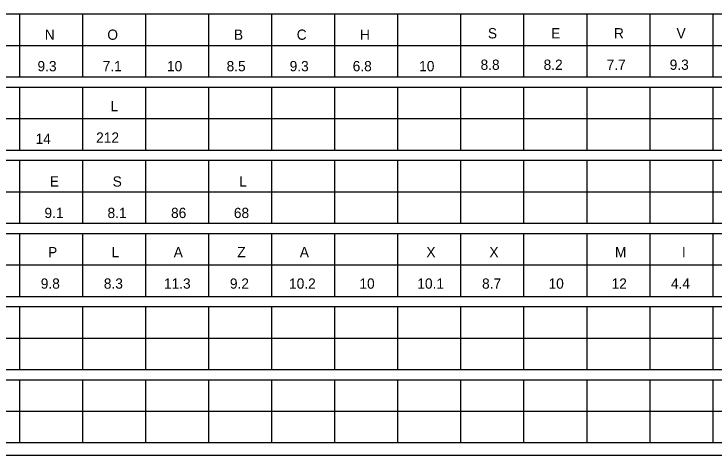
# Model space of a CAD drawing. Extents: x 17890628 to 17890817, y 17897493 to 17897992.
# Drawn here: x 17890684.37 to 17890717.8, y 17897548.86 to 17897569.94 of the extents above; entities that cross this region are included whole.
import ezdxf

# ---------------------------------------------------------------- set-up
doc = ezdxf.new("R2010")
doc.units = 0
doc.layers.add('GSSign', color=7, linetype='Continuous')
doc.layers.add('SheetLinesMisc2_dp', color=7, linetype='Continuous')

msp = doc.modelspace()

# ---------------------------------------------------------------- linework, layer by layer
at = {"layer": 'SheetLinesMisc2_dp'}
for p, q in [((17890661.804, 17897569.94), (17890735.8, 17897569.94)), ((17890684.628, 17897569.94), (17890684.628, 17897566.933)), ((17890687.638, 17897569.94), (17890687.638, 17897566.933)), ((17890690.648, 17897569.94), (17890690.648, 17897566.933)), ((17890693.658, 17897569.94), (17890693.658, 17897566.933)), ((17890696.669, 17897569.94), (17890696.669, 17897566.933)), ((17890699.679, 17897569.94), (17890699.679, 17897566.933)), ((17890702.689, 17897569.94), (17890702.689, 17897566.933)), ((17890705.699, 17897569.94), (17890705.699, 17897566.933)), ((17890708.709, 17897569.94), (17890708.709, 17897566.933)), ((17890711.719, 17897569.94), (17890711.719, 17897566.933)), ((17890714.729, 17897569.94), (17890714.729, 17897566.933)), ((17890717.739, 17897569.94), (17890717.739, 17897566.933)), ((17890661.804, 17897568.437), (17890735.8, 17897568.437)), ((17890661.804, 17897566.933), (17890735.8, 17897566.933)), ((17890661.804, 17897566.443), (17890735.8, 17897566.443)), ((17890684.628, 17897566.443), (17890684.628, 17897563.437)), ((17890687.638, 17897566.443), (17890687.638, 17897563.437)), ((17890690.648, 17897566.443), (17890690.648, 17897563.437)), ((17890693.658, 17897566.443), (17890693.658, 17897563.437)), ((17890696.669, 17897566.443), (17890696.669, 17897563.437)), ((17890699.679, 17897566.443), (17890699.679, 17897563.437)), ((17890702.689, 17897566.443), (17890702.689, 17897563.437)), ((17890705.699, 17897566.443), (17890705.699, 17897563.437)), ((17890708.709, 17897566.443), (17890708.709, 17897563.437)), ((17890711.719, 17897566.443), (17890711.719, 17897563.437)), ((17890714.729, 17897566.443), (17890714.729, 17897563.437)), ((17890717.739, 17897566.443), (17890717.739, 17897563.437)), ((17890661.804, 17897564.94), (17890735.8, 17897564.94)), ((17890661.804, 17897563.437), (17890735.8, 17897563.437)), ((17890661.804, 17897562.947), (17890735.8, 17897562.947)), ((17890684.628, 17897562.947), (17890684.628, 17897559.941)), ((17890687.638, 17897562.947), (17890687.638, 17897559.941)), ((17890690.648, 17897562.947), (17890690.648, 17897559.941)), ((17890693.658, 17897562.947), (17890693.658, 17897559.941)), ((17890696.669, 17897562.947), (17890696.669, 17897559.941)), ((17890699.679, 17897562.947), (17890699.679, 17897559.941)), ((17890702.689, 17897562.947), (17890702.689, 17897559.941)), ((17890705.699, 17897562.947), (17890705.699, 17897559.941)), ((17890708.709, 17897562.947), (17890708.709, 17897559.941)), ((17890711.719, 17897562.947), (17890711.719, 17897559.941)), ((17890714.729, 17897562.947), (17890714.729, 17897559.941)), ((17890717.739, 17897562.947), (17890717.739, 17897559.941)), ((17890661.804, 17897561.444), (17890735.8, 17897561.444)), ((17890661.804, 17897559.941), (17890735.8, 17897559.941)), ((17890661.804, 17897559.451), (17890735.8, 17897559.451)), ((17890684.628, 17897559.451), (17890684.628, 17897556.444)), ((17890687.638, 17897559.451), (17890687.638, 17897556.444)), ((17890690.648, 17897559.451), (17890690.648, 17897556.444)), ((17890693.658, 17897559.451), (17890693.658, 17897556.444)), ((17890696.669, 17897559.451), (17890696.669, 17897556.444)), ((17890699.679, 17897559.451), (17890699.679, 17897556.444)), ((17890702.689, 17897559.451), (17890702.689, 17897556.444)), ((17890705.699, 17897559.451), (17890705.699, 17897556.444)), ((17890708.709, 17897559.451), (17890708.709, 17897556.444)), ((17890711.719, 17897559.451), (17890711.719, 17897556.444)), ((17890714.729, 17897559.451), (17890714.729, 17897556.444)), ((17890717.739, 17897559.451), (17890717.739, 17897556.444)), ((17890661.804, 17897557.947), (17890735.8, 17897557.947)), ((17890661.804, 17897556.444), (17890735.8, 17897556.444)), ((17890661.804, 17897555.954), (17890735.8, 17897555.954)), ((17890684.628, 17897555.954), (17890684.628, 17897552.948)), ((17890687.638, 17897555.954), (17890687.638, 17897552.948)), ((17890690.648, 17897555.954), (17890690.648, 17897552.948)), ((17890693.658, 17897555.954), (17890693.658, 17897552.948)), ((17890696.669, 17897555.954), (17890696.669, 17897552.948)), ((17890699.679, 17897555.954), (17890699.679, 17897552.948)), ((17890702.689, 17897555.954), (17890702.689, 17897552.948)), ((17890705.699, 17897555.954), (17890705.699, 17897552.948)), ((17890708.709, 17897555.954), (17890708.709, 17897552.948)), ((17890711.719, 17897555.954), (17890711.719, 17897552.948)), ((17890714.729, 17897555.954), (17890714.729, 17897552.948)), ((17890717.739, 17897555.954), (17890717.739, 17897552.948)), ((17890661.804, 17897554.451), (17890735.8, 17897554.451)), ((17890661.804, 17897552.948), (17890735.8, 17897552.948)), ((17890661.804, 17897552.458), (17890735.8, 17897552.458)), ((17890684.628, 17897552.458), (17890684.628, 17897549.452)), ((17890687.638, 17897552.458), (17890687.638, 17897549.452)), ((17890690.648, 17897552.458), (17890690.648, 17897549.452)), ((17890693.658, 17897552.458), (17890693.658, 17897549.452)), ((17890696.669, 17897552.458), (17890696.669, 17897549.452)), ((17890699.679, 17897552.458), (17890699.679, 17897549.452)), ((17890702.689, 17897552.458), (17890702.689, 17897549.452)), ((17890705.699, 17897552.458), (17890705.699, 17897549.452)), ((17890708.709, 17897552.458), (17890708.709, 17897549.452)), ((17890711.719, 17897552.458), (17890711.719, 17897549.452)), ((17890714.729, 17897552.458), (17890714.729, 17897549.452)), ((17890717.739, 17897552.458), (17890717.739, 17897549.452)), ((17890661.804, 17897550.955), (17890735.8, 17897550.955)), ((17890661.804, 17897549.452), (17890735.8, 17897549.452)), ((17890661.083, 17897548.861), (17890736.311, 17897548.861))]:
    msp.add_line(p, q, dxfattribs=at)

# ---------------------------------------------------------------- texts
at = {"layer": 'GSSign'}
for s, height, p in [('N', 0.49, (17890685.843, 17897568.706)), ('O', 0.49, (17890688.83, 17897568.706)), ('B', 0.49, (17890694.874, 17897568.706)), ('C', 0.49, (17890697.873, 17897568.706)), ('H', 0.49, (17890700.895, 17897568.706)), ('S', 0.49, (17890707.001, 17897568.773)), ('E', 0.49, (17890710.023, 17897568.773)), ('R', 0.49, (17890713.022, 17897568.773)), ('V', 0.49, (17890716.009, 17897568.773)), ('8.8', 0.4902, (17890706.651, 17897567.27)), ('8.2', 0.4902, (17890709.661, 17897567.27)), ('9.3', 0.4902, (17890715.682, 17897567.27)), ('9.3', 0.4902, (17890685.493, 17897567.203)), ('7.1', 0.4902, (17890688.608, 17897567.203)), ('10', 0.4902, (17890691.677, 17897567.203)), ('8.5', 0.4902, (17890694.524, 17897567.203)), ('9.3', 0.4902, (17890697.534, 17897567.203)), ('6.8', 0.4902, (17890700.545, 17897567.203)), ('10', 0.4902, (17890703.718, 17897567.203)), ('7.7', 0.4902, (17890712.672, 17897567.27)), ('L', 0.49, (17890688.982, 17897565.291)), ('14', 0.4902, (17890685.402, 17897563.73)), ('212', 0.4902, (17890688.294, 17897563.788)), ('E', 0.49, (17890686.084, 17897561.69)), ('S', 0.49, (17890689.083, 17897561.69)), ('L', 0.49, (17890695.127, 17897561.69)), ('9.1', 0.4902, (17890685.827, 17897560.187)), ('8.1', 0.4902, (17890688.838, 17897560.187)), ('86', 0.4902, (17890691.871, 17897560.187)), ('68', 0.4902, (17890694.87, 17897560.187)), ('P', 0.49, (17890686, 17897558.313)), ('L', 0.49, (17890689.034, 17897558.313)), ('A', 0.49, (17890691.998, 17897558.313)), ('Z', 0.49, (17890695.032, 17897558.313)), ('A', 0.49, (17890698.019, 17897558.313)), ('X', 0.49, (17890704.063, 17897558.313)), ('X', 0.49, (17890707.073, 17897558.313)), ('M', 0.49, (17890713.07, 17897558.313)), ('I', 0.49, (17890716.267, 17897558.313)), ('9.8', 0.4902, (17890685.65, 17897556.81)), ('8.3', 0.4902, (17890688.661, 17897556.81)), ('11.3', 0.4902, (17890691.531, 17897556.81)), ('9.2', 0.4902, (17890694.681, 17897556.81)), ('10.2', 0.4902, (17890697.505, 17897556.81)), ('10', 0.4902, (17890700.866, 17897556.81)), ('10.1', 0.4902, (17890703.631, 17897556.81)), ('8.7', 0.4902, (17890706.723, 17897556.81)), ('10', 0.4902, (17890709.897, 17897556.81)), ('12', 0.4902, (17890712.907, 17897556.81)), ('4.4', 0.4902, (17890715.742, 17897556.81))]:
    msp.add_text(s, height=height, dxfattribs=at).set_placement(p)

doc.saveas('drawing.dxf')
